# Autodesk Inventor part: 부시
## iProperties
Company: 한국ATC센터
Created: 2014-08
Part Number: 부시
Document SubType Name: Modeling
Designer: KYOUNG IL JANG
Density: 1 g/cm^3
Checked By: KYOUNG IL JANG
Author: KYOUNG IL JANG
